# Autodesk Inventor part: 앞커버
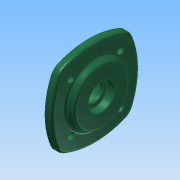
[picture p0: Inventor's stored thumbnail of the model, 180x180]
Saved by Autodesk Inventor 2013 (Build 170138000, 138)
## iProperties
Created: 2015-11
Part Number: 앞커버
Material: 알루미늄 6061
Document SubType Name: Modeling
Designer: mduedu
Density: 2.71 g/cm^3
Mass: 305.846 g
Surface Area: 251.177 cm^2
Volume: 112.858 cm^3
Author: mduedu
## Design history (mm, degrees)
sketch "스케치1"
  geometry: L1 (50, 50)-(-50, 50); L2 (-50, 50)-(-50, -50); L3 (-50, -50)-(50, -50); L4 (50, -50)-(50, 50); L5 (0, 50)-(0, -50); L6 (50, 0)-(-50, 0); A1 r 90 centre (-40, 0) between (40.415, -40.415) and (40.415, 40.415); A2 r 90 centre (40, 0) between (-40.415, 40.415) and (-40.415, -40.415); A3 r 90 centre (0, -40) between (40.415, 40.415) and (-40.415, 40.415); A4 r 90 centre (0, 40) between (-40.415, -40.415) and (40.415, -40.415); 2 further points
  constraints: 12 end point, 8 point on circle, 5 midpoint, 4 centre point, 2 horizontal alignment, 2 parallel, 2 perpendicular, 2 symmetric about line, 2 tangent, 2 vertical alignment, 1 equal radius, 1 horizontal, 2 other
  dimensions: "d0" = 100 distance of L3.end L1.start; "d2" = 90 radius of A1
extrude "돌출1" new body sketch "스케치1" distance "d3" = 8; taper "d4" = 0 deg
sketch "스케치2"
  geometry: C1 r 35 at (0, 0); 1 further point
  constraints: 1 centre point, 1 coincident
  dimensions: "d5" = 70 diameter of C1
extrude "돌출2" join sketch "스케치2" distance "d6" = 7; taper "d7" = -30 deg
sketch "스케치3"
  geometry: L1 (0, 0)-(0, 40); L2 (0, 0)-(-28.284, 28.284); A1 r 40 centre (0, 0) between (0, 40) and (-28.284, 28.284); 2 further points
  constraints: 4 end point, 2 coincident, 2 point on circle, 1 centre point, 1 vertical
  dimensions: "d8" = 80 diameter of A1; "d9" = 45 deg angle of L1 L2
hole "구멍1" sketch "스케치3" at (-28.284, 28.284) diameter "d11" = 4.5; stored, may be unused: countersink angle "d15" = 90 deg, drill point angle "d17" = 118 deg; dims "d12" = 6, "d13" = 8, "d14" = 4.4, "d16" = 8
sketch "스케치4"
  geometry: C1 r 35 at (0, 0); 1 further point
  constraints: 1 centre point, 1 coincident
  dimensions: "d21" = 70 diameter of C1
extrude "돌출3" join sketch "스케치4" distance "d23" = 12; taper "d24" = 0 deg
hole "구멍2" diameter "d27" = 30; stored, may be unused: countersink angle "d31" = 90 deg, drill point angle "d33" = 0 deg; dims "d25" = 10, "d26" = 10, "d28" = 6, "d29" = 40, "d30" = 12, "d32" = 15
fillet "모깎기2" dims "d35" = 15
fillet "모깎기3" dims "d36" = 3
fillet "모깎기4" dims "d37" = 3
fillet "모깎기5" dims "d38" = 0.3
chamfer "모따기1" distance "d39" = 1; stored, may be unused: second distance "d40" = 2, angle "d41" = 45 deg
hole "구멍3" diameter "d44" = 20; stored, may be unused: countersink angle "d48" = 90 deg, drill point angle "d50" = 118 deg; dims "d45" = 6, "d46" = 30, "d47" = 8.7, "d49" = 8, "d55" = 10, "d56" = 10
fillet "모깎기6" dims "d51" = 0.3
chamfer "모따기2" distance "d52" = 0.7; stored, may be unused: second distance "d53" = 2, angle "d54" = 30 deg
node "솔리드1"
pattern_circular "원형 패턴1" dims angle "d19" = 360 deg
